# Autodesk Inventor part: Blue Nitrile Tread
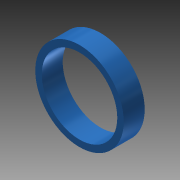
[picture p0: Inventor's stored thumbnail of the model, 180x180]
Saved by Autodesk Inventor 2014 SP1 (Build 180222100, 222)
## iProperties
Created: 2014-07
Part Number: Blue Nitrile Tread
Material: Rubber
Document SubType Name: Modeling
Designer: Michael
Density: 0.93 g/cm^3
Appearance: Cyan
Mass: 58.0327 g
Surface Area: 207.633 cm^2
Volume: 62.4007 cm^3
Author: Michael
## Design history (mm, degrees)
sketch "Sketch1"
  geometry: C1 r 45.72 at (0, 0); C2 r 53.594 at (0, 0); 1 further point
  constraints: 2 centre point, 2 coincident
  dimensions: "d0" = 91.44 diameter of C1; "d1" = 107.188 diameter of C2 (computed from d0)
extrude "Extrusion1" new body sketch "Sketch1" distance "d2" = 25.4; taper "d3" = 0 deg
body "Solid1"
